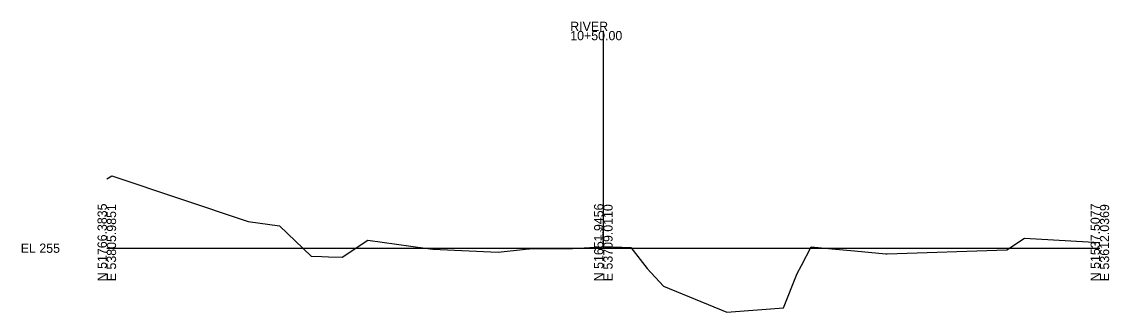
# Model space of a CAD drawing. Extents: x 5628 to 5956, y 92469 to 104012.
# Drawn here: x 5627.6 to 5956.2, y 99959.2 to 100047.2 of the extents above; entities that cross this region are included whole.
import ezdxf

# ---------------------------------------------------------------- set-up
doc = ezdxf.new("R2010")
doc.units = 0
for name, color, linetype in [('Level 10', 7, 'Continuous'), ('Level 60', 7, 'Continuous'), ('Level 63', 7, 'Continuous')]:
    doc.layers.add(name, color=color, linetype=linetype)

msp = doc.modelspace()

# ---------------------------------------------------------------- linework, layer by layer
at = {"layer": 'Level 60'}
for p, q in [((5653.34, 99999.56), (5654.81, 100000.52)), ((5654.81, 100000.52), (5696.02, 99986.69)), ((5696.02, 99986.69), (5705.54, 99985.34)), ((5705.54, 99985.34), (5715.05, 99976.23)), ((5724.4, 99975.84), (5732.16, 99981.07)), ((5732.16, 99981.07), (5749.51, 99978.64)), ((5925.2, 99978.13), (5930.56, 99981.68)), ((5930.56, 99981.68), (5953.34, 99980.31)), ((5715.05, 99976.23), (5718.29, 99976.05)), ((5749.51, 99978.64), (5751.86, 99978.29)), ((5751.86, 99978.29), (5771.53, 99977.39)), ((5771.53, 99977.39), (5779.86, 99978.33)), ((5779.86, 99978.33), (5781.02, 99978.37)), ((5781.02, 99978.37), (5794.07, 99978.53)), ((5794.07, 99978.53), (5802.76, 99979.06)), ((5802.76, 99979.06), (5803.37, 99979.09)), ((5803.37, 99979.09), (5811.64, 99978.79)), ((5811.64, 99978.79), (5816.62, 99972.46)), ((5863.16, 99973.34), (5866.15, 99979.01)), ((5866.15, 99979.01), (5872.4, 99978.41)), ((5872.4, 99978.41), (5879.18, 99977.76)), ((5879.18, 99977.76), (5888.72, 99976.9)), ((5888.72, 99976.9), (5889.08, 99976.91)), ((5889.08, 99976.91), (5925.2, 99978.13)), ((5718.29, 99976.05), (5720.35, 99976.03)), ((5720.35, 99976.03), (5724.4, 99975.84)), ((5861.88, 99970.89), (5863.16, 99973.34)), ((5816.62, 99972.46), (5821.52, 99967.07)), ((5857.78, 99960.58), (5861.88, 99970.89)), ((5821.52, 99967.07), (5840.62, 99959.19)), ((5840.62, 99959.19), (5857.78, 99960.58))]:
    msp.add_line(p, q, dxfattribs=at)
at = {"layer": 'Level 63'}
for p, q in [((5803.34, 99978.6), (5803.34, 100044.36)), ((5653.34, 99978.6), (5803.34, 99978.6)), ((5803.34, 99978.6), (5953.34, 99978.6))]:
    msp.add_line(p, q, dxfattribs=at)

# ---------------------------------------------------------------- texts
at = {"layer": 'Level 10'}
msp.add_text('255.25', height=1.2, rotation=90, dxfattribs=at).set_placement((5803.54, 99980.09))
at = {"layer": 'Level 63'}
for s, p in [('RIVER', (5793.34, 100044.36)), ('10+50.00', (5793.34, 100041.56)), ('EL 255', (5627.33, 99977.2))]:
    msp.add_text(s, height=2.8, dxfattribs=at).set_placement(p)
for s, p in [('N 51766.3835', (5653.34, 99968.6)), ('E 53805.9851', (5656.14, 99968.6)), ('N 51651.9456', (5803.34, 99968.59)), ('E 53709.0110', (5806.14, 99968.6)), ('N 51537.5077', (5953.34, 99968.6)), ('E 53612.0369', (5956.14, 99968.6))]:
    msp.add_text(s, height=2.8, rotation=90, dxfattribs=at).set_placement(p)

doc.saveas('drawing.dxf')
